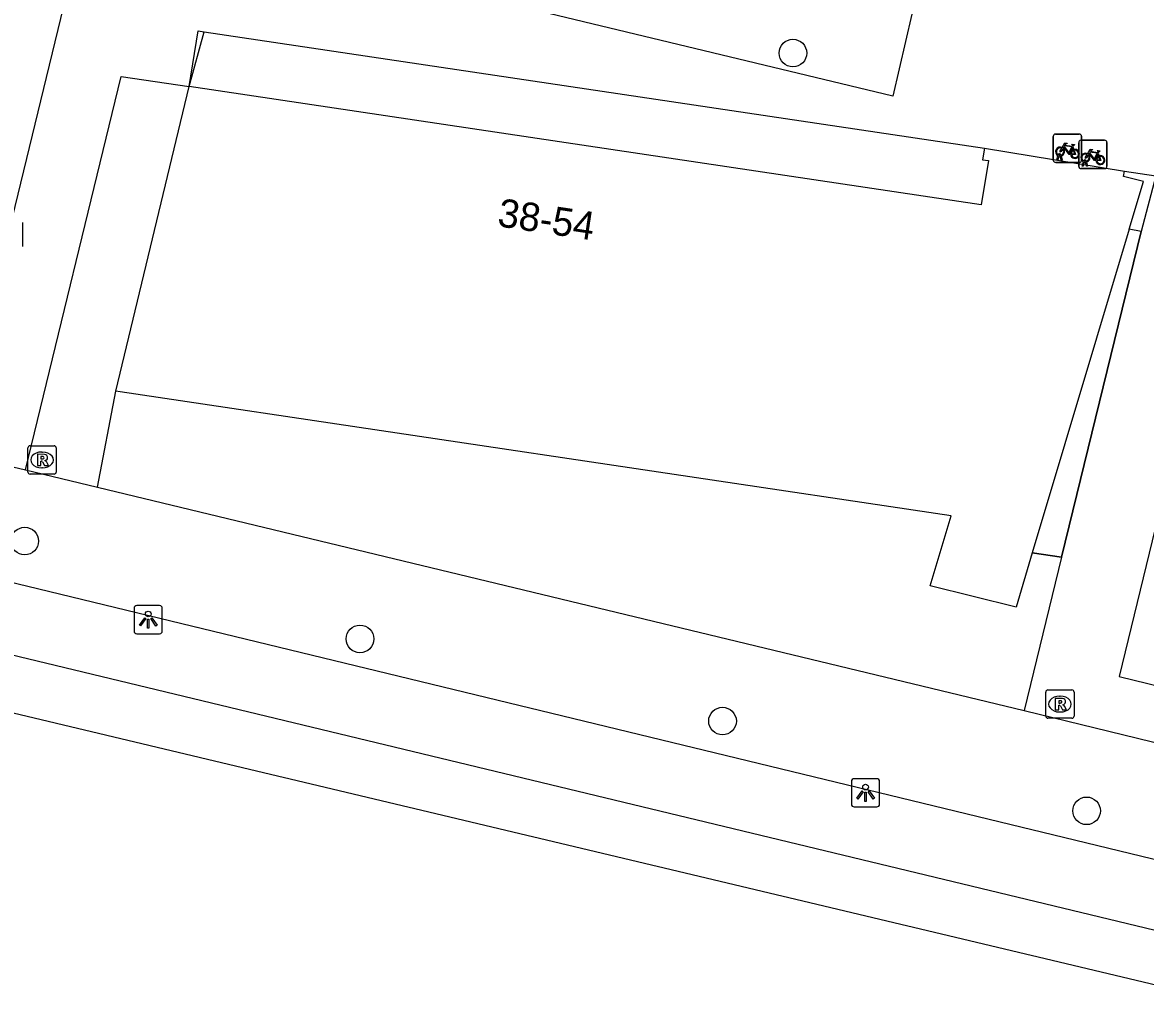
# Model space of a CAD drawing. Extents: x 162812 to 163818, y 381639 to 382470.
# Drawn here: x 163371.5 to 163411.21, y 382135.2 to 382169.41 of the extents above; entities that cross this region are included whole.
import ezdxf

# ---------------------------------------------------------------- set-up
doc = ezdxf.new("R2010")
doc.units = 0
for name, color, linetype in [('IMGEO_Boom', 7, 'Continuous'), ('IMGEO_Fietsenrek', 7, 'Continuous'), ('IMGEO_Groenvoorziening', 7, 'Continuous'), ('IMGEO_Kolk', 7, 'Continuous'), ('IMGEO_Lichtpunt', 7, 'Continuous'), ('IMGEO_Pand', 7, 'Continuous'), ('IMGEO_Pand_nummerreeks', 7, 'Continuous'), ('IMGEO_Pand_overbouw', 7, 'Continuous'), ('IMGEO_Rioolput', 7, 'Continuous'), ('IMGEO_Voetpad_open', 7, 'Continuous')]:
    doc.layers.add(name, color=color, linetype=linetype)

msp = doc.modelspace()

# ---------------------------------------------------------------- linework, layer by layer
at = {"layer": 'IMGEO_Boom'}
for centre in [(163398.74, 382168.329), (163371.577, 382151.068), (163383.432, 382147.607), (163396.251, 382144.701), (163409.125, 382141.526)]:
    msp.add_circle(centre, 0.489, dxfattribs=at)
at = {"layer": 'IMGEO_Fietsenrek'}
for p, q in [((163407.948, 382164.538), (163407.948, 382165.379)), ((163407.948, 382165.379), (163407.948, 382164.538)), ((163408.023, 382165.463), (163408.864, 382165.463)), ((163408.864, 382165.463), (163408.023, 382165.463)), ((163408.948, 382165.388), (163408.948, 382164.547)), ((163408.948, 382164.547), (163408.948, 382165.388)), ((163408.635, 382165.012), (163408.671, 382164.917)), ((163408.845, 382164.319), (163408.845, 382165.16)), ((163408.845, 382165.16), (163408.845, 382164.319)), ((163408.92, 382165.244), (163409.761, 382165.244)), ((163409.761, 382165.244), (163408.92, 382165.244)), ((163409.845, 382165.169), (163409.845, 382164.328)), ((163409.845, 382164.328), (163409.845, 382165.169)), ((163408.075, 382164.547), (163408.114, 382164.707)), ((163408.109, 382164.547), (163408.075, 382164.547)), ((163408.144, 382164.695), (163408.109, 382164.547)), ((163408.186, 382164.719), (163408.185, 382164.723)), ((163408.227, 382164.547), (163408.193, 382164.689)), ((163408.217, 382164.73), (163408.218, 382164.723)), ((163408.225, 382164.693), (163408.26, 382164.547)), ((163408.26, 382164.547), (163408.227, 382164.547)), ((163408.972, 382164.328), (163409.011, 382164.488)), ((163409.083, 382164.5), (163409.082, 382164.504)), ((163409.114, 382164.511), (163409.115, 382164.504)), ((163409.532, 382164.793), (163409.568, 382164.698)), ((163408.873, 382164.463), (163408.032, 382164.463)), ((163408.032, 382164.463), (163408.873, 382164.463)), ((163409.77, 382164.244), (163408.929, 382164.244)), ((163408.929, 382164.244), (163409.77, 382164.244)), ((163409.006, 382164.328), (163408.972, 382164.328)), ((163409.041, 382164.476), (163409.006, 382164.328)), ((163409.124, 382164.328), (163409.09, 382164.47)), ((163409.122, 382164.474), (163409.157, 382164.328)), ((163409.157, 382164.328), (163409.124, 382164.328))]:
    msp.add_line(p, q, dxfattribs=at)
for points in [[(163408.282, 382164.937), (163408.23, 382164.847), (163408.19, 382164.822), (163408.191, 382164.869), (163408.246, 382164.963)], [(163408.261, 382164.989), (163408.356, 382165.153), (163408.442, 382165.139), (163408.444, 382165.13), (163408.388, 382165.119), (163408.361, 382165.074), (163408.617, 382165.033)], [(163408.557, 382164.745), (163408.507, 382164.745), (163408.316, 382164.996), (163408.297, 382164.964)], [(163408.604, 382165.008), (163408.347, 382165.049), (163408.33, 382165.02), (163408.497, 382164.8), (163408.604, 382165.008)], [(163408.652, 382164.91), (163408.622, 382164.987), (163408.513, 382164.769), (163408.556, 382164.769)], [(163408.682, 382164.889), (163408.737, 382164.744), (163408.587, 382164.744)], [(163408.617, 382165.033), (163408.642, 382165.082), (163408.636, 382165.086), (163408.613, 382165.09), (163408.601, 382165.097), (163408.6, 382165.1), (163408.602, 382165.105), (163408.697, 382165.09), (163408.699, 382165.08), (163408.689, 382165.067), (163408.677, 382165.061), (163408.663, 382165.067), (163408.635, 382165.012)], [(163409.158, 382164.77), (163409.253, 382164.934), (163409.339, 382164.92), (163409.341, 382164.911), (163409.285, 382164.9), (163409.258, 382164.855), (163409.514, 382164.814)], [(163409.514, 382164.814), (163409.539, 382164.863), (163409.533, 382164.867), (163409.51, 382164.871), (163409.498, 382164.878), (163409.497, 382164.881), (163409.499, 382164.886), (163409.594, 382164.871), (163409.596, 382164.861), (163409.586, 382164.848), (163409.574, 382164.842), (163409.56, 382164.848), (163409.532, 382164.793)], [(163408.586, 382164.769), (163408.706, 382164.768), (163408.662, 382164.882)], [(163409.179, 382164.718), (163409.127, 382164.628), (163409.087, 382164.603), (163409.088, 382164.65), (163409.143, 382164.744)], [(163409.454, 382164.526), (163409.404, 382164.526), (163409.213, 382164.777), (163409.194, 382164.745)], [(163409.501, 382164.789), (163409.244, 382164.83), (163409.227, 382164.801), (163409.394, 382164.581), (163409.501, 382164.789)], [(163409.549, 382164.691), (163409.519, 382164.768), (163409.41, 382164.55), (163409.453, 382164.55)], [(163409.483, 382164.55), (163409.603, 382164.549), (163409.559, 382164.663)], [(163409.579, 382164.67), (163409.634, 382164.525), (163409.484, 382164.525)]]:
    msp.add_lwpolyline(points, dxfattribs=at)
for centre, radius, start, end in [((163408.026, 382165.385), 0.0779, 92.4484, 184.2845), ((163408.026, 382165.385), 0.0779, 92.4484, 184.2845), ((163408.87, 382165.385), 0.0779, 2.4484, 94.2845), ((163408.87, 382165.385), 0.0779, 2.4484, 94.2845), ((163408.188, 382164.848), 0.159, 62.6766, 242.1369), ((163408.188, 382164.848), 0.129, 63.3192, 238.903), ((163408.188, 382164.848), 0.129, 283.6043, 43.4302), ((163408.188, 382164.848), 0.159, 283.5766, 46.6042), ((163408.715, 382164.764), 0.159, 113.3408, 178.3217), ((163408.715, 382164.764), 0.159, 187.0065, 105.7708), ((163408.715, 382164.764), 0.129, 188.6715, 104.5883), ((163408.923, 382165.166), 0.0779, 92.4484, 184.2845), ((163408.923, 382165.166), 0.0779, 92.4484, 184.2845), ((163409.767, 382165.166), 0.0779, 2.4484, 94.2845), ((163409.767, 382165.166), 0.0779, 2.4484, 94.2845), ((163408.026, 382164.541), 0.0779, 182.4484, 274.2845), ((163408.026, 382164.541), 0.0779, 182.4484, 274.2845), ((163408.168, 382164.719), 0.0499, 12.8025, 158.6934), ((163408.188, 382164.848), 0.159, 253.9967, 271.7867), ((163408.168, 382164.719), 0.0174, 12.8025, 163.4502), ((163408.188, 382164.848), 0.129, 253.415, 269.0204), ((163408.715, 382164.764), 0.129, 113.923, 177.9556), ((163408.87, 382164.541), 0.0779, 272.4484, 4.2845), ((163408.87, 382164.541), 0.0779, 272.4484, 4.2845), ((163409.085, 382164.629), 0.159, 62.6766, 242.1369), ((163409.085, 382164.629), 0.129, 63.3192, 238.903), ((163409.065, 382164.5), 0.0499, 12.8025, 158.6934), ((163409.065, 382164.5), 0.0174, 12.8025, 163.4502), ((163409.085, 382164.629), 0.129, 253.415, 269.0204), ((163409.085, 382164.629), 0.129, 283.6043, 43.4302), ((163409.085, 382164.629), 0.159, 283.5766, 46.6042), ((163409.612, 382164.545), 0.159, 113.3408, 178.3217), ((163409.612, 382164.545), 0.159, 187.0065, 105.7708), ((163409.612, 382164.545), 0.129, 113.923, 177.9556), ((163409.612, 382164.545), 0.129, 188.6715, 104.5883), ((163408.923, 382164.322), 0.0779, 182.4484, 274.2845), ((163408.923, 382164.322), 0.0779, 182.4484, 274.2845), ((163409.085, 382164.629), 0.159, 253.9967, 271.7867), ((163409.767, 382164.322), 0.0779, 272.4484, 4.2845), ((163409.767, 382164.322), 0.0779, 272.4484, 4.2845)]:
    msp.add_arc(centre, radius, start, end, dxfattribs=at)
at = {"layer": 'IMGEO_Groenvoorziening'}
for points in [[(163427.031, 382131.676), (163378.53, 382143.226), (163360.431, 382147.536), (163359.411, 382147.779), (163344.765, 382151.266), (163342.628, 382151.775), (163333.895, 382153.854), (163313.112, 382158.803), (163295.55, 382162.985), (163294.668, 382163.195)], [(163374.154, 382152.972), (163374.799, 382156.371)], [(163371.606, 382153.585), (163374.154, 382152.972)], [(163374.154, 382152.972), (163406.922, 382145.077)]]:
    msp.add_lwpolyline(points, dxfattribs=at)
at = {"layer": 'IMGEO_Kolk'}
msp.add_line((163371.496, 382162.34), (163371.496, 382161.488), dxfattribs=at)
msp.add_lwpolyline([(163371.496, 382162.34), (163371.496, 382161.488)], dxfattribs=at)
at = {"layer": 'IMGEO_Lichtpunt'}
for p, q in [((163375.445, 382148.691), (163375.445, 382147.884)), ((163375.445, 382148.691), (163375.445, 382147.884)), ((163376.347, 382148.786), (163375.539, 382148.786)), ((163376.347, 382148.786), (163375.539, 382148.786)), ((163376.441, 382147.884), (163376.441, 382148.691)), ((163376.441, 382147.884), (163376.441, 382148.691)), ((163375.539, 382147.79), (163376.347, 382147.79)), ((163375.539, 382147.79), (163376.347, 382147.79)), ((163401.712, 382142.663), (163400.904, 382142.663)), ((163401.712, 382142.663), (163400.904, 382142.663)), ((163400.81, 382142.568), (163400.81, 382141.761)), ((163400.81, 382142.568), (163400.81, 382141.761)), ((163401.806, 382141.761), (163401.806, 382142.568)), ((163401.806, 382141.761), (163401.806, 382142.568)), ((163400.904, 382141.667), (163401.712, 382141.667)), ((163400.904, 382141.667), (163401.712, 382141.667))]:
    msp.add_line(p, q, dxfattribs=at)
for points in [[(163375.819, 382148.355), (163375.858, 382148.327), (163375.67, 382148.065), (163375.632, 382148.092), (163375.819, 382148.355)], [(163375.921, 382148.307), (163375.968, 382148.307), (163375.968, 382147.985), (163375.921, 382147.985), (163375.921, 382148.307)], [(163376.031, 382148.327), (163376.069, 382148.354), (163376.256, 382148.092), (163376.217, 382148.064), (163376.031, 382148.327)], [(163401.184, 382142.232), (163401.223, 382142.204), (163401.035, 382141.942), (163400.997, 382141.969), (163401.184, 382142.232)], [(163401.286, 382142.184), (163401.333, 382142.184), (163401.333, 382141.862), (163401.286, 382141.862), (163401.286, 382142.184)], [(163401.396, 382142.204), (163401.434, 382142.231), (163401.621, 382141.969), (163401.582, 382141.941), (163401.396, 382142.204)]]:
    msp.add_lwpolyline(points, dxfattribs=at)
for centre in [(163375.944, 382148.489), (163401.309, 382142.366)]:
    msp.add_circle(centre, 0.0994, dxfattribs=at)
for centre, start, end in [((163375.539, 382148.691), 90, 180), ((163375.539, 382148.691), 90, 180), ((163376.347, 382148.691), 0, 90), ((163376.347, 382148.691), 0, 90), ((163375.539, 382147.884), 180, 270), ((163375.539, 382147.884), 180, 270), ((163376.347, 382147.884), 270, 0), ((163376.347, 382147.884), 270, 360), ((163400.904, 382142.568), 90, 180), ((163400.904, 382142.568), 90, 180), ((163401.712, 382142.568), 0, 90), ((163401.712, 382142.568), 0, 90), ((163400.904, 382141.761), 180, 270), ((163400.904, 382141.761), 180, 270), ((163401.712, 382141.761), 270, 0), ((163401.712, 382141.761), 270, 360)]:
    msp.add_arc(centre, 0.0946, start, end, dxfattribs=at)
at = {"layer": 'IMGEO_Pand'}
for points in [[(163374.799, 382156.371), (163377.389, 382167.151)], [(163405.517, 382164.971), (163405.442, 382164.556), (163405.658, 382164.528), (163405.399, 382162.964), (163377.389, 382167.151)], [(163405.517, 382164.971), (163410.462, 382164.153)], [(163410.631, 382162.099), (163411.138, 382163.792), (163410.432, 382163.969), (163410.462, 382164.153)], [(163410.631, 382162.099), (163407.206, 382150.656)], [(163407.206, 382150.656), (163406.631, 382148.735), (163403.598, 382149.483), (163404.091, 382151.13), (163404.338, 382151.955), (163374.957, 382156.347), (163374.799, 382156.371)]]:
    msp.add_lwpolyline(points, dxfattribs=at)
at = {"layer": 'IMGEO_Pand_overbouw'}
msp.add_lwpolyline([(163411.056, 382162.02), (163410.631, 382162.099), (163407.206, 382150.656), (163408.24, 382150.498)], close=True, dxfattribs=at)
at = {"layer": 'IMGEO_Rioolput'}
for p, q in [((163371.691, 382153.511), (163371.691, 382154.363)), ((163371.766, 382154.437), (163372.618, 382154.437)), ((163372.179, 382154.217), (163372.204, 382154.217)), ((163372.692, 382154.363), (163372.692, 382153.511)), ((163372.618, 382153.437), (163371.766, 382153.437)), ((163372.202, 382153.657), (163372.177, 382153.657)), ((163407.682, 382144.876), (163407.682, 382145.728)), ((163407.757, 382145.802), (163408.609, 382145.802)), ((163408.17, 382145.582), (163408.195, 382145.582)), ((163408.683, 382145.728), (163408.683, 382144.876)), ((163408.609, 382144.802), (163407.757, 382144.802)), ((163408.193, 382145.022), (163408.168, 382145.022))]:
    msp.add_line(p, q, dxfattribs=at)
for points in [[(163371.691, 382153.511), (163371.691, 382154.363)], [(163371.766, 382154.437), (163372.618, 382154.437)], [(163372.692, 382154.363), (163372.692, 382153.511)], [(163372.28, 382154.135), (163372.028, 382154.137), (163372.028, 382153.737)], [(163372.028, 382153.737), (163372.152, 382153.737), (163372.152, 382153.899), (163372.163, 382153.899)], [(163372.206, 382154.056), (163372.152, 382154.056), (163372.152, 382153.975)], [(163372.152, 382153.975), (163372.204, 382153.975)], [(163372.21, 382153.87), (163372.281, 382153.737), (163372.421, 382153.737), (163372.356, 382153.863)], [(163372.618, 382153.437), (163371.766, 382153.437)], [(163407.682, 382144.876), (163407.682, 382145.728)], [(163407.757, 382145.802), (163408.609, 382145.802)], [(163408.271, 382145.5), (163408.019, 382145.502), (163408.019, 382145.102)], [(163408.683, 382145.728), (163408.683, 382144.876)], [(163408.019, 382145.102), (163408.143, 382145.102), (163408.143, 382145.264), (163408.154, 382145.264)], [(163408.197, 382145.421), (163408.143, 382145.421), (163408.143, 382145.34)], [(163408.143, 382145.34), (163408.195, 382145.34)], [(163408.201, 382145.235), (163408.272, 382145.102), (163408.412, 382145.102), (163408.347, 382145.228)], [(163408.609, 382144.802), (163407.757, 382144.802)]]:
    msp.add_lwpolyline(points, dxfattribs=at)
for centre, radius, start, end in [((163371.768, 382154.361), 0.0765, 91.552, 178.448), ((163371.768, 382154.361), 0.0765, 91.552, 178.448), ((163372.616, 382154.361), 0.0765, 1.552, 88.448), ((163372.616, 382154.361), 0.0765, 1.552, 88.448), ((163372.162, 382153.846), 0.0533, 26.0293, 88.6989), ((163372.188, 382154.164), 0.19, 274.7715, 282.9687), ((163372.212, 382153.96), 0.0964, 77.0061, 93.1865), ((163372.226, 382154.017), 0.0378, 276.6634, 79.6772), ((163372.279, 382154.025), 0.109, 350.3612, 89.416), ((163372.277, 382154.025), 0.112, 277.5842, 350.9817), ((163372.261, 382153.81), 0.108, 29.5134, 73.7905), ((163371.768, 382153.513), 0.0765, 181.552, 268.448), ((163371.768, 382153.513), 0.0765, 181.552, 268.448), ((163372.616, 382153.513), 0.0765, 271.552, 358.448), ((163372.616, 382153.513), 0.0765, 271.552, 358.448), ((163407.759, 382145.726), 0.0765, 91.552, 178.448), ((163407.759, 382145.726), 0.0765, 91.552, 178.448), ((163408.27, 382145.39), 0.109, 350.3612, 89.416), ((163408.607, 382145.726), 0.0765, 1.552, 88.448), ((163408.607, 382145.726), 0.0765, 1.552, 88.448), ((163408.153, 382145.211), 0.0533, 26.0293, 88.6989), ((163408.179, 382145.529), 0.19, 274.7715, 282.9687), ((163408.203, 382145.325), 0.0964, 77.0061, 93.1865), ((163408.217, 382145.382), 0.0378, 276.6634, 79.6772), ((163408.268, 382145.39), 0.112, 277.5842, 350.9817), ((163408.252, 382145.175), 0.108, 29.5134, 73.7905), ((163407.759, 382144.878), 0.0765, 181.552, 268.448), ((163407.759, 382144.878), 0.0765, 181.552, 268.448), ((163408.607, 382144.878), 0.0765, 271.552, 358.448), ((163408.607, 382144.878), 0.0765, 271.552, 358.448)]:
    msp.add_arc(centre, radius, start, end, dxfattribs=at)
for centre, major_axis, ratio, start_param, end_param in [((163372.178, 382153.937), (-0.387, 0.002), 0.722429, 4.712389, 7.853982), ((163372.203, 382153.937), (-0.39, 0.002), 0.717154, 1.570796, 4.712389), ((163408.169, 382145.302), (-0.387, 0.002), 0.722429, 4.712389, 7.853982), ((163408.194, 382145.302), (-0.39, 0.002), 0.717154, 1.570796, 4.712389)]:
    msp.add_ellipse(centre, major_axis=major_axis, ratio=ratio, start_param=start_param, end_param=end_param, dxfattribs=at)
at = {"layer": 'IMGEO_Voetpad_open'}
for points in [[(163402.95, 382169.707), (163402.273, 382166.808), (163378.585, 382172.515), (163379.275, 382175.422)], [(163373.348, 382171.653), (163369.709, 382156.692)], [(163377.389, 382167.151), (163377.71, 382169.118), (163377.926, 382169.086)], [(163377.389, 382167.151), (163377.926, 382169.086)], [(163377.926, 382169.086), (163405.517, 382164.971)], [(163371.606, 382153.585), (163374.987, 382167.505), (163377.389, 382167.151)], [(163410.462, 382164.153), (163411.572, 382163.984), (163411.056, 382162.02)], [(163411.056, 382162.02), (163408.24, 382150.498)], [(163411.056, 382162.02), (163410.631, 382162.099)], [(163413.657, 382160.192), (163410.282, 382146.275), (163421.953, 382143.42)], [(163337.772, 382155.076), (163343.556, 382153.683), (163344.914, 382153.356), (163359.96, 382149.732), (163361, 382149.482), (163427.406, 382133.488)], [(163365.885, 382150.868), (163366.869, 382154.713), (163371.606, 382153.585)], [(163412.973, 382139.449), (163365.885, 382150.868)], [(163408.24, 382150.498), (163407.206, 382150.656)], [(163408.24, 382150.498), (163406.922, 382145.077)], [(163406.922, 382145.077), (163413.921, 382143.368), (163412.973, 382139.449)]]:
    msp.add_lwpolyline(points, dxfattribs=at)

# ---------------------------------------------------------------- texts
at = {"layer": 'IMGEO_Pand_nummerreeks'}
msp.add_text('38-54', height=1, rotation=351.4982, dxfattribs=at).set_placement((163388.262, 382162.209))

doc.saveas('drawing.dxf')
